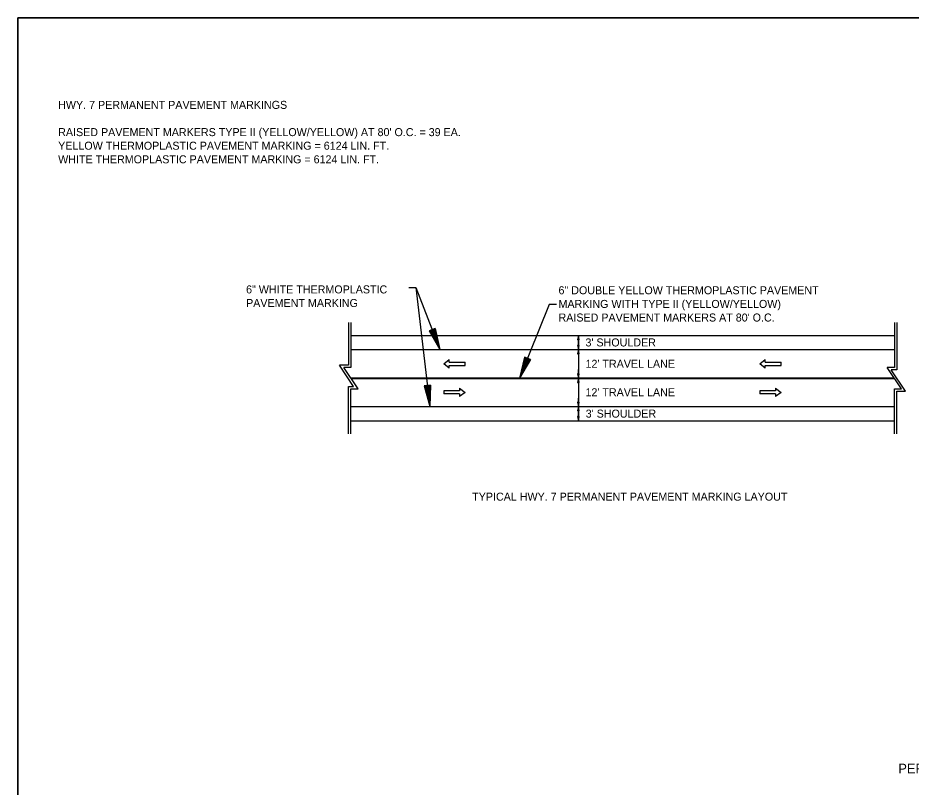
# Model space of a CAD drawing. Extents: x 2261938 to 2263136, y -3124572 to -3124216.
# Drawn here: x 2261937.6 to 2262063.2, y -3124460.6 to -3124352.5 of the extents above; entities that cross this region are included whole.
import ezdxf

# ---------------------------------------------------------------- set-up
doc = ezdxf.new("R2010")
doc.units = 0
for name, color, linetype in [('Default', 7, 'Continuous'), ('DSN_DRFT_Junk-No-Plot', 7, 'Continuous'), ('R_Border Notes', 7, 'Continuous'), ('R_Draft', 7, 'Continuous')]:
    doc.layers.add(name, color=color, linetype=linetype)

msp = doc.modelspace()

# ---------------------------------------------------------------- linework, layer by layer
at = {"layer": 'Default'}
for p, q in [((2261992.58, -3124390.37), (2261993.58, -3124390.37)), ((2261993.58, -3124390.37), (2261996.93, -3124399.09)), ((2261993.58, -3124390.37), (2261995.53, -3124407.09)), ((2262012.33, -3124392.74), (2262008.17, -3124403.09)), ((2262013.33, -3124392.74), (2262012.33, -3124392.74)), ((2261984.12, -3124395.26), (2261984.12, -3124401.26)), ((2261984.45, -3124395.26), (2261984.45, -3124401.59)), ((2262060.84, -3124395.26), (2262060.84, -3124401.59)), ((2262061.17, -3124395.26), (2262061.17, -3124401.93)), ((2261996.28, -3124396.13), (2261995.43, -3124396.45)), ((2261995.43, -3124396.45), (2261996.93, -3124399.09)), ((2261995.5, -3124396.43), (2261996.75, -3124398.63)), ((2261995.58, -3124396.4), (2261996.57, -3124398.14)), ((2261995.65, -3124396.37), (2261996.39, -3124397.68)), ((2261995.72, -3124396.35), (2261996.2, -3124397.2)), ((2261995.79, -3124396.32), (2261996.02, -3124396.74)), ((2261995.92, -3124396.27), (2261996.02, -3124396.74)), ((2261995.99, -3124396.24), (2261996.2, -3124397.2)), ((2261996.06, -3124396.21), (2261996.39, -3124397.68)), ((2261996.13, -3124396.19), (2261996.57, -3124398.14)), ((2261996.21, -3124396.16), (2261996.75, -3124398.63)), ((2261996.28, -3124396.13), (2261996.93, -3124399.09)), ((2262008.87, -3124400.14), (2262008.17, -3124403.09)), ((2262009.71, -3124400.48), (2262008.17, -3124403.09)), ((2262008.94, -3124400.17), (2262008.36, -3124402.63)), ((2262009.64, -3124400.45), (2262008.36, -3124402.63)), ((2262009.01, -3124400.2), (2262008.55, -3124402.15)), ((2262009.57, -3124400.42), (2262008.55, -3124402.15)), ((2262009.08, -3124400.23), (2262008.74, -3124401.69)), ((2262009.5, -3124400.39), (2262008.74, -3124401.69)), ((2262009.71, -3124400.48), (2262008.87, -3124400.14)), ((2262009.15, -3124400.26), (2262008.93, -3124401.22)), ((2262009.43, -3124400.36), (2262008.93, -3124401.22)), ((2262009.23, -3124400.28), (2262009.11, -3124400.75)), ((2262009.36, -3124400.34), (2262009.11, -3124400.75)), ((2261984.83, -3124404.26), (2261982.83, -3124401.26)), ((2261984.12, -3124401.26), (2261982.83, -3124401.26)), ((2261984.45, -3124401.59), (2261983.45, -3124401.59)), ((2261985.45, -3124404.59), (2261983.45, -3124401.59)), ((2261997.5, -3124401.09), (2261998.28, -3124400.49)), ((2261998.28, -3124401.69), (2261997.5, -3124401.09)), ((2261998.28, -3124400.87), (2261998.28, -3124400.49)), ((2261998.28, -3124400.87), (2262000.49, -3124400.87)), ((2261998.28, -3124401.32), (2262000.49, -3124401.32)), ((2261998.28, -3124401.69), (2261998.28, -3124401.32)), ((2262000.49, -3124401.32), (2262000.49, -3124400.87)), ((2262041.91, -3124401.09), (2262042.69, -3124400.49)), ((2262042.69, -3124401.69), (2262041.91, -3124401.09)), ((2262042.69, -3124400.87), (2262042.69, -3124400.49)), ((2262042.69, -3124400.87), (2262044.9, -3124400.87)), ((2262042.69, -3124401.32), (2262044.9, -3124401.32)), ((2262042.69, -3124401.69), (2262042.69, -3124401.32)), ((2262044.9, -3124401.32), (2262044.9, -3124400.87)), ((2262060.84, -3124401.59), (2262059.84, -3124401.59)), ((2262061.84, -3124404.59), (2262059.84, -3124401.59)), ((2262062.4, -3124404.93), (2262060.4, -3124401.93)), ((2262061.17, -3124401.93), (2262060.4, -3124401.93)), ((2261995.63, -3124404.06), (2261994.73, -3124404.17)), ((2261994.73, -3124404.17), (2261995.53, -3124407.09)), ((2261994.81, -3124404.16), (2261995.47, -3124406.6)), ((2261994.88, -3124404.15), (2261995.41, -3124406.08)), ((2261994.96, -3124404.14), (2261995.35, -3124405.59)), ((2261995.03, -3124404.13), (2261995.29, -3124405.08)), ((2261995.11, -3124404.12), (2261995.24, -3124404.59)), ((2261995.25, -3124404.11), (2261995.24, -3124404.59)), ((2261995.33, -3124404.1), (2261995.29, -3124405.08)), ((2261995.4, -3124404.09), (2261995.35, -3124405.59)), ((2261995.48, -3124404.08), (2261995.41, -3124406.08)), ((2261995.55, -3124404.07), (2261995.47, -3124406.6)), ((2261995.63, -3124404.06), (2261995.53, -3124407.09)), ((2261984.12, -3124404.26), (2261984.83, -3124404.26)), ((2261984.12, -3124410.93), (2261984.12, -3124404.26)), ((2261984.45, -3124410.93), (2261984.45, -3124404.59)), ((2261984.45, -3124404.59), (2261985.45, -3124404.59)), ((2261999.71, -3124404.87), (2261997.5, -3124404.87)), ((2261997.5, -3124404.87), (2261997.5, -3124405.32)), ((2261999.71, -3124405.32), (2261997.5, -3124405.32)), ((2261999.71, -3124404.49), (2261999.71, -3124404.87)), ((2261999.71, -3124404.49), (2262000.49, -3124405.09)), ((2262000.49, -3124405.09), (2261999.71, -3124405.69)), ((2261999.71, -3124405.32), (2261999.71, -3124405.69)), ((2262044.12, -3124404.87), (2262041.91, -3124404.87)), ((2262041.91, -3124404.87), (2262041.91, -3124405.32)), ((2262044.12, -3124405.32), (2262041.91, -3124405.32)), ((2262044.12, -3124404.49), (2262044.12, -3124404.87)), ((2262044.12, -3124404.49), (2262044.9, -3124405.09)), ((2262044.9, -3124405.09), (2262044.12, -3124405.69)), ((2262044.12, -3124405.32), (2262044.12, -3124405.69)), ((2262060.84, -3124410.93), (2262060.84, -3124404.59)), ((2262060.84, -3124404.59), (2262061.84, -3124404.59)), ((2262061.17, -3124410.93), (2262061.17, -3124404.93)), ((2262061.17, -3124404.93), (2262062.4, -3124404.93))]:
    msp.add_line(p, q, dxfattribs=at)
at = {"layer": 'DSN_DRFT_Junk-No-Plot'}
msp.add_line((2262016.43, -3124397.09), (2262016.43, -3124409.09), dxfattribs=at)
for points in [[(2261937.65, -3124352.47), (2262107.65, -3124352.47), (2262107.65, -3124462.47), (2261937.65, -3124462.47)], [(2261937.65, -3124352.47), (2261937.65, -3124462.47), (2262107.65, -3124462.47), (2262107.65, -3124352.47)]]:
    msp.add_lwpolyline(points, close=True, dxfattribs=at)
for points in [[(2262016.43, -3124397.09), (2262016.31, -3124397.69), (2262016.55, -3124397.69), (2262016.43, -3124397.09), (2262016.43, -3124398.29)], [(2262016.43, -3124399.09), (2262016.55, -3124398.49), (2262016.31, -3124398.49), (2262016.43, -3124399.09), (2262016.43, -3124397.89)], [(2262016.43, -3124399.09), (2262016.31, -3124399.69), (2262016.55, -3124399.69), (2262016.43, -3124399.09), (2262016.43, -3124400.29)], [(2262016.43, -3124403.09), (2262016.55, -3124402.49), (2262016.31, -3124402.49), (2262016.43, -3124403.09), (2262016.43, -3124401.89)], [(2262016.43, -3124403.09), (2262016.31, -3124403.69), (2262016.55, -3124403.69), (2262016.43, -3124403.09), (2262016.43, -3124404.29)], [(2262016.43, -3124407.09), (2262016.55, -3124406.49), (2262016.31, -3124406.49), (2262016.43, -3124407.09), (2262016.43, -3124405.89)], [(2262016.43, -3124407.09), (2262016.31, -3124407.69), (2262016.55, -3124407.69), (2262016.43, -3124407.09), (2262016.43, -3124408.29)], [(2262016.43, -3124409.09), (2262016.55, -3124408.49), (2262016.31, -3124408.49), (2262016.43, -3124409.09), (2262016.43, -3124407.89)]]:
    msp.add_lwpolyline(points, dxfattribs=at)
at = {"layer": 'R_Draft'}
for p, q in [((2261984.45, -3124397.09), (2262060.84, -3124397.09)), ((2261984.45, -3124399.09), (2262060.84, -3124399.09)), ((2261984.42, -3124403.04), (2262060.81, -3124403.04)), ((2261984.48, -3124403.14), (2262060.87, -3124403.14)), ((2261984.45, -3124407.09), (2262060.84, -3124407.09)), ((2261984.45, -3124409.09), (2262060.84, -3124409.09))]:
    msp.add_line(p, q, dxfattribs=at)

# ---------------------------------------------------------------- texts
at = {"layer": 'Default'}
for s, p in [('HWY. 7 PERMANENT PAVEMENT MARKINGS', (2261943.31, -3124365.26)), ("RAISED PAVEMENT MARKERS TYPE II (YELLOW/YELLOW) AT 80' O.C. = 39 EA.", (2261943.31, -3124369.09)), ('YELLOW THERMOPLASTIC PAVEMENT MARKING = 6124 LIN. FT.', (2261943.31, -3124371)), ('WHITE THERMOPLASTIC PAVEMENT MARKING = 6124 LIN. FT.', (2261943.31, -3124372.91)), ('6" WHITE THERMOPLASTIC', (2261969.72, -3124391.19)), ('6" DOUBLE YELLOW THERMOPLASTIC PAVEMENT', (2262013.63, -3124391.31)), ('PAVEMENT MARKING', (2261969.72, -3124393.1)), ('MARKING WITH TYPE II (YELLOW/YELLOW)', (2262013.63, -3124393.23)), ("RAISED PAVEMENT MARKERS AT 80' O.C.", (2262013.63, -3124395.14))]:
    msp.add_text(s, height=1.125, dxfattribs=at).set_placement(p)
at = {"layer": 'R_Border Notes'}
msp.add_text('PERMANENT PAVEMENT MARKING DETAILS', height=1.35, dxfattribs=at).set_placement((2262061.39, -3124458.62))
at = {"layer": 'R_Draft'}
for s, p in [("3' SHOULDER", (2262017.42, -3124398.64)), ("12' TRAVEL LANE", (2262017.42, -3124401.64)), ("12' TRAVEL LANE", (2262017.42, -3124405.64)), ("3' SHOULDER", (2262017.45, -3124408.64)), ('TYPICAL HWY. 7 PERMANENT PAVEMENT MARKING LAYOUT', (2262001.5, -3124420.31))]:
    msp.add_text(s, height=1.125, dxfattribs=at).set_placement(p)

doc.saveas('drawing.dxf')
